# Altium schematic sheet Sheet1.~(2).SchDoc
size A; SheetNumber: 1; SheetTotal: 1
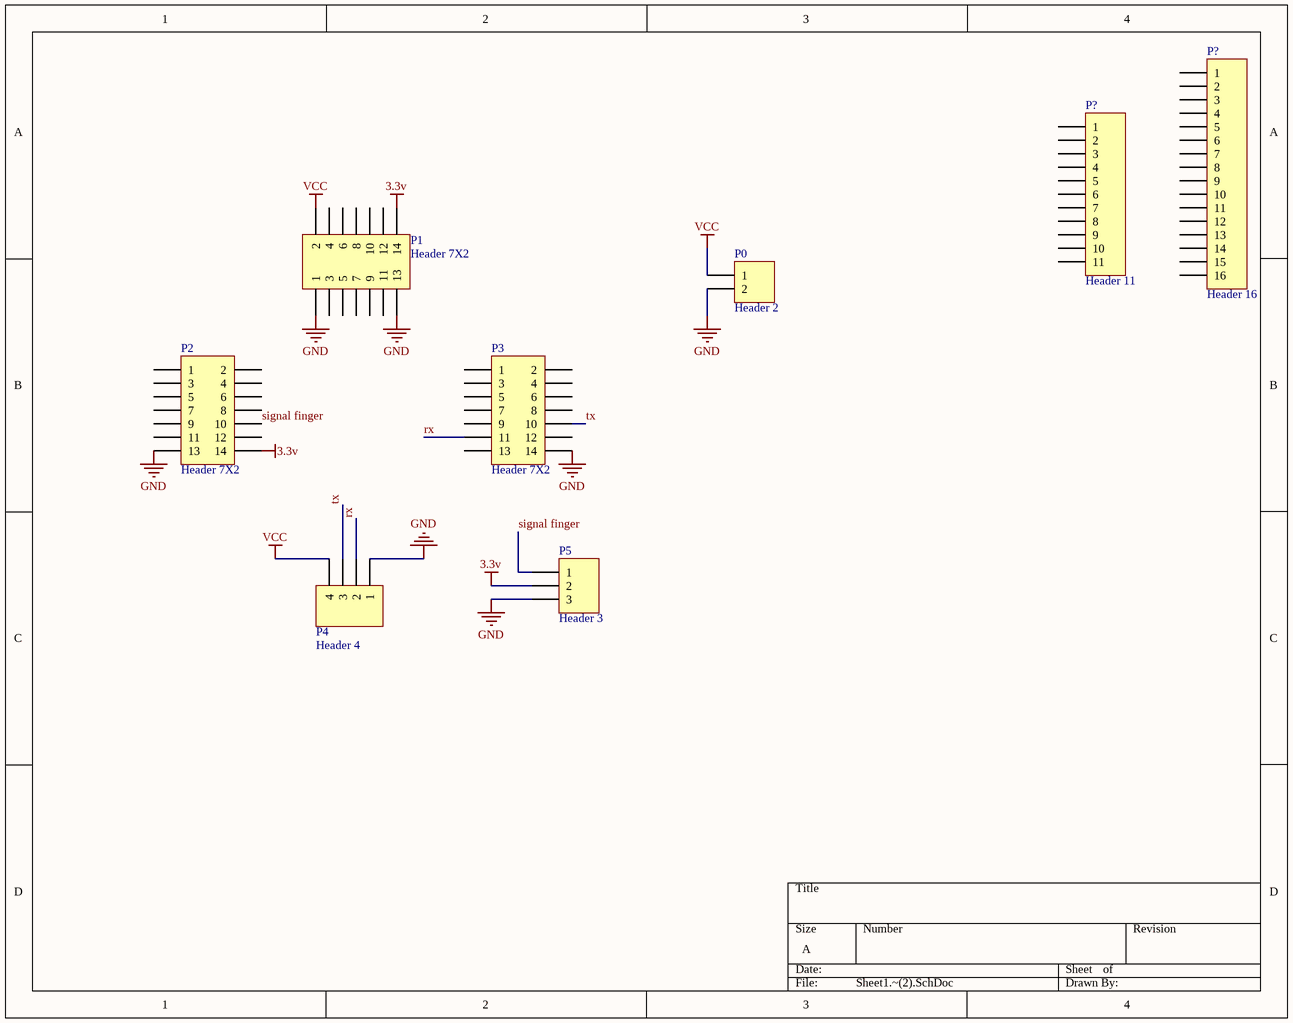
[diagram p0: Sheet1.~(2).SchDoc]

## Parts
(Parts that share a designator on the sheet are numbered #1, #2 ... from top to bottom, then left to right.)
P0  Header 2  [HDR1X2]
P1  Header 7X2  [HDR2X7]
P2  Header 7X2  [HDR2X7]
P3  Header 7X2  [HDR2X7]
P4  Header 4  [HDR1X4]
P5  Header 3  [HDR1X3]
P?#1  Header 16  [HDR1X16]
P?#2  Header 11  [HDR1X11]

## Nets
3.3v: P1.14 P2.14 P5.2
GND: P0.2 P1.1 P1.13 P2.13 P3.14 P4.1 P5.3
VCC: P0.1 P1.2 P4.4
rx: P3.11 P4.2
signal finger: P2.10 P5.1
tx: P3.10 P4.3

Not connected (* = marked no-connect by the designer): P1 3 4 5 6 7 8 9 10 11 12; P2 1 2 3 4 5 6 7 8 9 11 12; P3 1 2 3 4 5 6 7 8 9 12 13; P?#1 1 2 3 4 5 6 7 8 9 10 11 12 13 14 15 16; P?#2 1 2 3 4 5 6 7 8 9 10 11

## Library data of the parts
P0 = Header 2: Header, 2-Pin
P1-P3 = Header 7X2: Header, 7-Pin, Dual row
P4 = Header 4: Header, 4-Pin
P5 = Header 3: Header, 3-Pin
P?#1 = Header 16: Header, 16-Pin
P?#2 = Header 11: Header, 11-Pin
